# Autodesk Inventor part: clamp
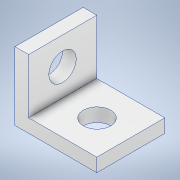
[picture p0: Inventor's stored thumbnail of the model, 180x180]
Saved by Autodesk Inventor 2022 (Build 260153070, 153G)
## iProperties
Created: 2021-06
Part Number: clamp
Material: Aluminum 6061
Document SubType Name: Modeling
Designer: Administrator
Density: 2.7 g/cm^3
Appearance: Aluminum - Flat
Author: Administrator
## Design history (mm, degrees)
sketch "Sketch1"
  geometry: L1 (4.47, 12.7)-(-8.23, 12.7); L2 (-8.23, 12.7)-(-8.23, 0); L3 (-8.23, 0)-(4.47, 0); L4 (4.47, 0)-(4.47, 12.7); 1 further point
  constraints: 8 end point, 2 parallel, 1 horizontal, 1 perpendicular
  dimensions: "d0" = 12.7 distance between parallel lines of L2 L4; "d1" = 12.7 distance between parallel lines of L1 L3; "d2" = 4.46965 distance from line of point (0, 0) L4; "d3" = 12.7 distance from line of point (0, 0) L1
extrude "Extrusion1" new body sketch "Sketch1" distance "d4" = 2.54; taper "d5" = 0 deg
sketch "Sketch2"
  geometry: L1 (-12.7, -8.23)-(0, -8.23) reference; L2 (-12.7, -8.23)-(-0.031, -8.23); L3 (-0.031, -8.23)-(-0.031, -5.718); L4 (-0.031, -5.718)-(-12.7, -5.718); L5 (-12.7, -5.718)-(-12.7, -8.23); 2 further points
  constraints: 8 end point, 2 parallel, 1 horizontal, 1 perpendicular
extrude "Extrusion2" join sketch "Sketch2" distance "d6" = 12.7; taper "d7" = 0 deg
sketch "Sketch3"
  geometry: 2 further points
hole "Hole1" sketch "Sketch3" at (-6.385, -0.656) diameter "d8" = 5.08; stored, may be unused: countersink angle "d12" = 82 deg, drill point angle "d14" = 118 deg; dims "d9" = 19.05, "d10" = 9.525, "d11" = 6.35, "d13" = 25.4
sketch "Sketch4"
  geometry: 2 further points
hole "Hole2" sketch "Sketch4" at (6.419, 6.316) diameter "d15" = 5.08; stored, may be unused: countersink angle "d19" = 82 deg, drill point angle "d21" = 118 deg; dims "d16" = 19.05, "d17" = 9.525, "d18" = 6.35, "d20" = 25.4
body "Solid1"
